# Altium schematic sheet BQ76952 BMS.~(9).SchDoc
size A3; SheetNumber: 9; SheetTotal: 9
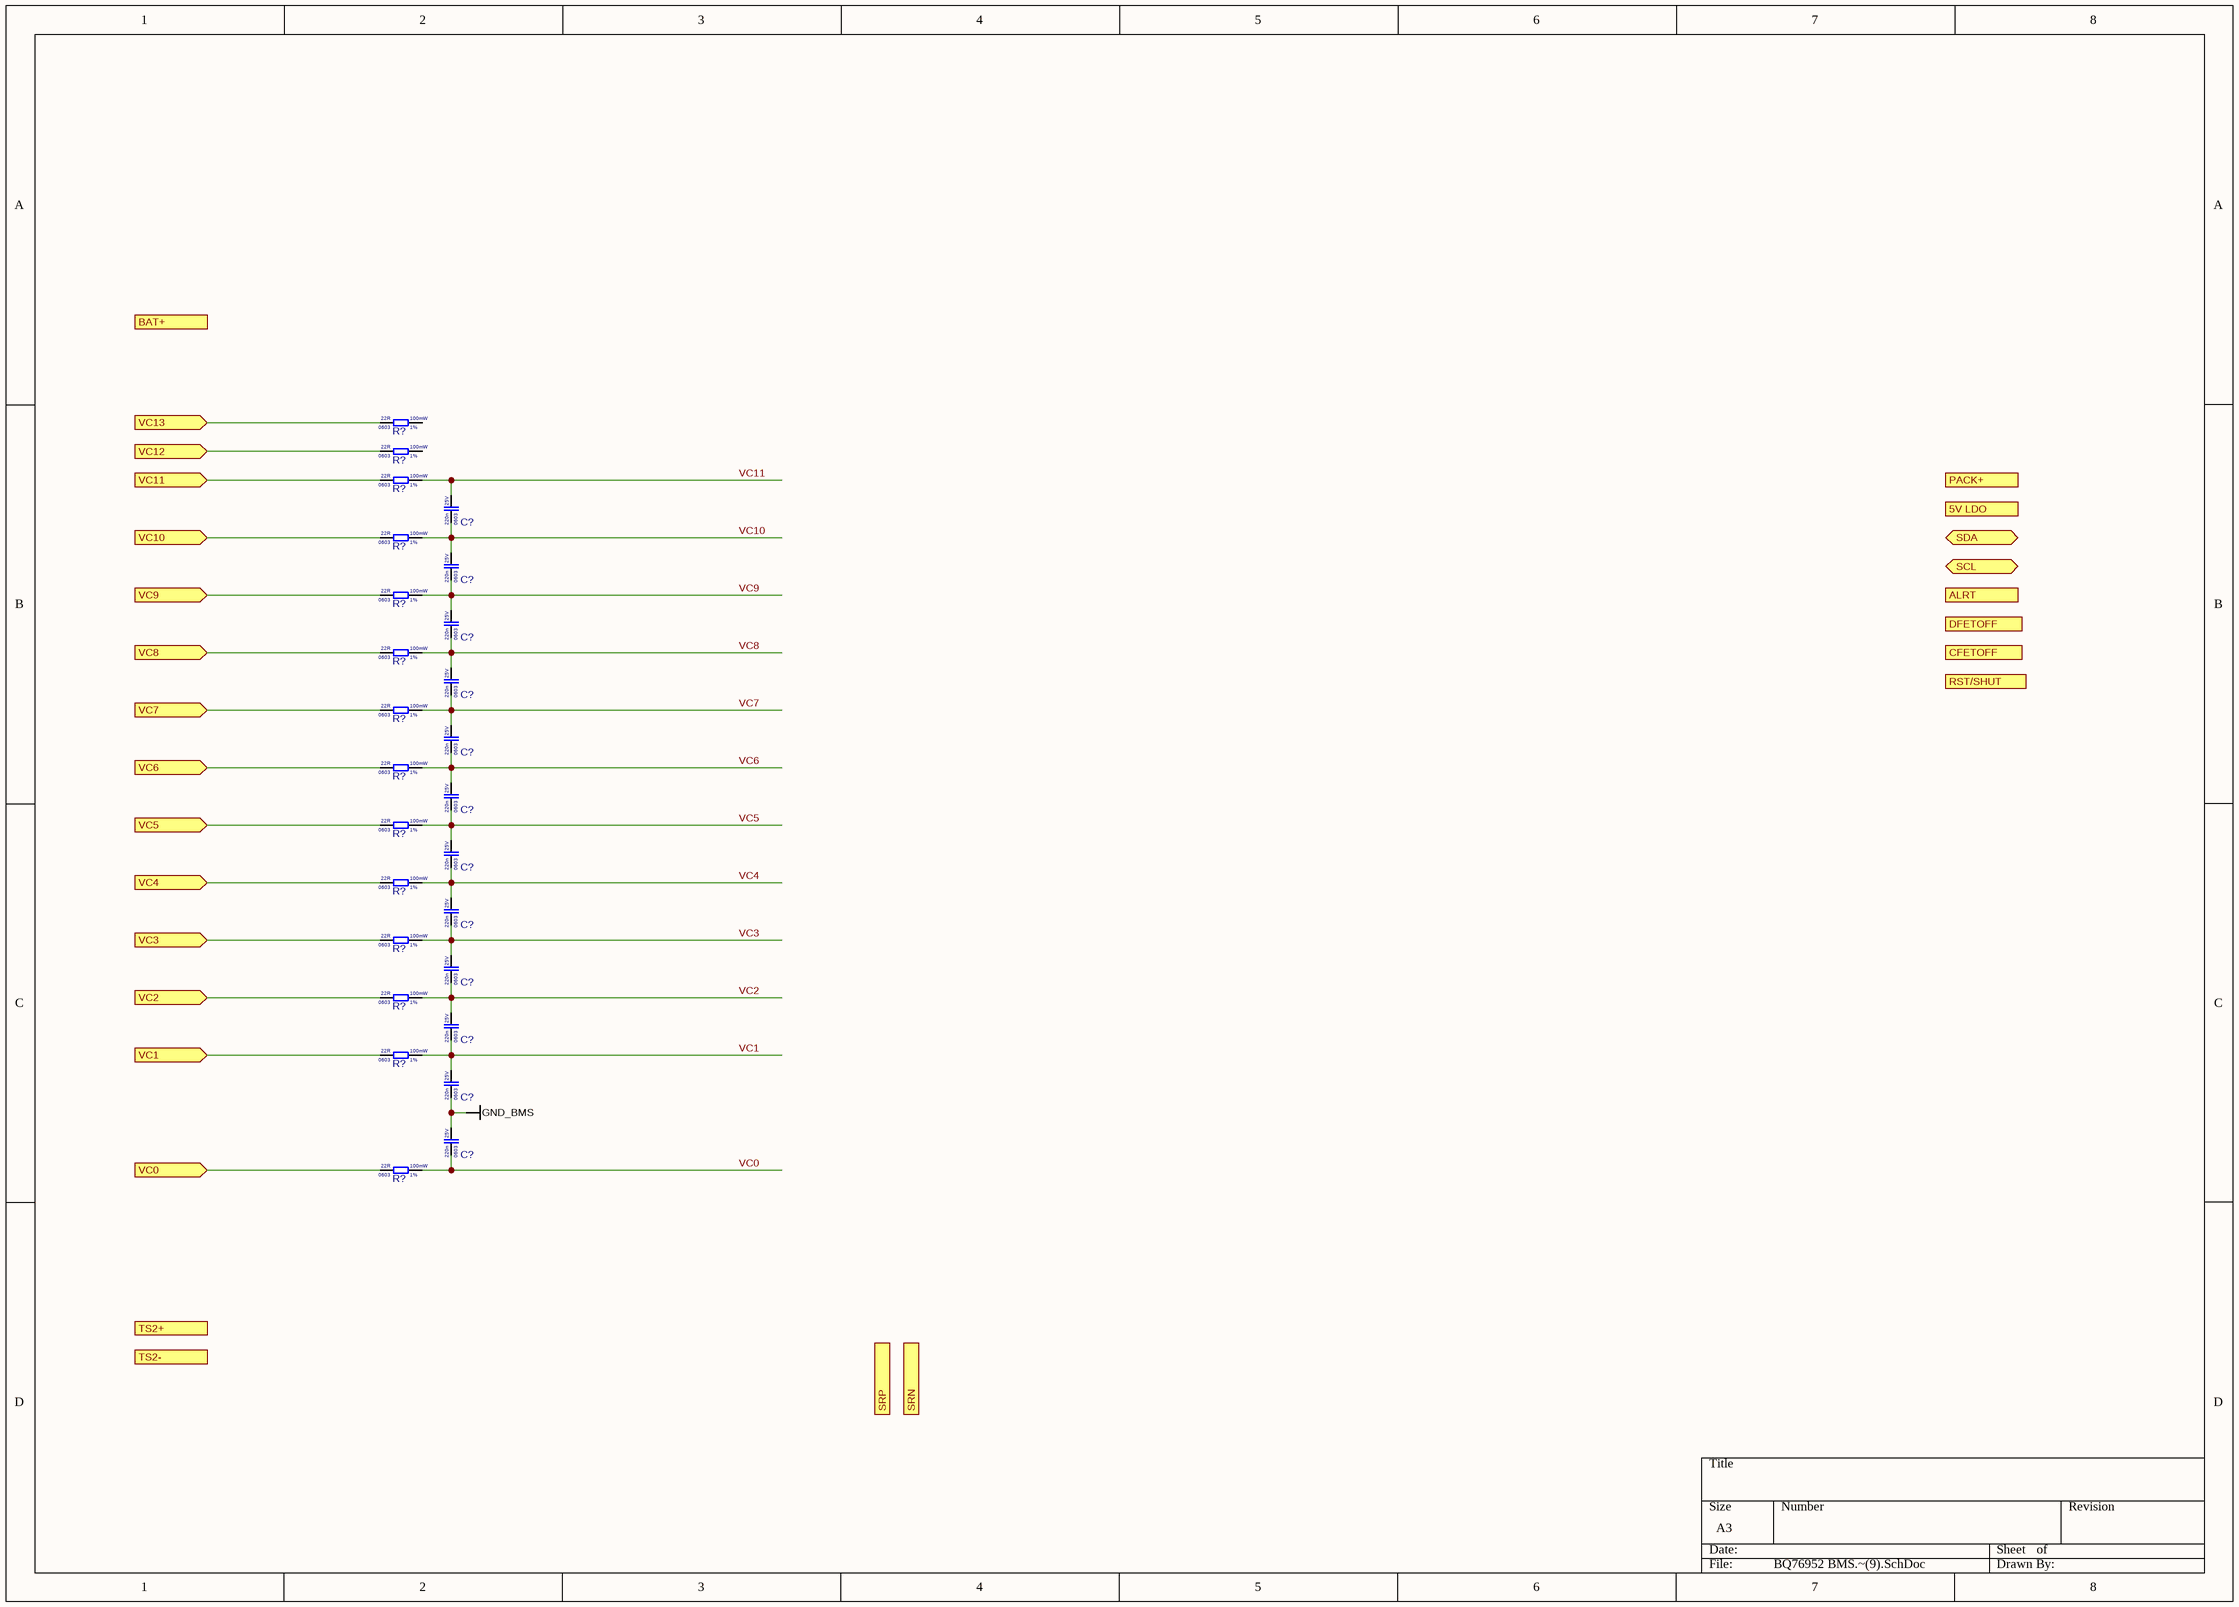
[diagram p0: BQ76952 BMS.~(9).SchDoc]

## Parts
(Parts that share a designator on the sheet are numbered #1, #2 ... from top to bottom, then left to right.)
C?#1  Voltage Rating: 25V  Case Code (Imperial): 0603  Capacitance: 220n  [CAP 0603]  (hidden comment: CL10B224KA8NNNC)
C?#2  Voltage Rating: 25V  Case Code (Imperial): 0603  Capacitance: 220n  [CAP 0603]  (hidden comment: CL10B224KA8NNNC)
C?#3  Voltage Rating: 25V  Case Code (Imperial): 0603  Capacitance: 220n  [CAP 0603]  (hidden comment: CL10B224KA8NNNC)
C?#4  Voltage Rating: 25V  Case Code (Imperial): 0603  Capacitance: 220n  [CAP 0603]  (hidden comment: CL10B224KA8NNNC)
C?#5  Voltage Rating: 25V  Case Code (Imperial): 0603  Capacitance: 220n  [CAP 0603]  (hidden comment: CL10B224KA8NNNC)
C?#6  Voltage Rating: 25V  Case Code (Imperial): 0603  Capacitance: 220n  [CAP 0603]  (hidden comment: CL10B224KA8NNNC)
C?#7  Voltage Rating: 25V  Case Code (Imperial): 0603  Capacitance: 220n  [CAP 0603]  (hidden comment: CL10B224KA8NNNC)
C?#8  Voltage Rating: 25V  Case Code (Imperial): 0603  Capacitance: 220n  [CAP 0603]  (hidden comment: CL10B224KA8NNNC)
C?#9  Voltage Rating: 25V  Case Code (Imperial): 0603  Capacitance: 220n  [CAP 0603]  (hidden comment: CL10B224KA8NNNC)
C?#10  Voltage Rating: 25V  Case Code (Imperial): 0603  Capacitance: 220n  [CAP 0603]  (hidden comment: CL10B224KA8NNNC)
C?#11  Voltage Rating: 25V  Case Code (Imperial): 0603  Capacitance: 220n  [CAP 0603]  (hidden comment: CL10B224KA8NNNC)
C?#12  Voltage Rating: 25V  Case Code (Imperial): 0603  Capacitance: 220n  [CAP 0603]  (hidden comment: CL10B224KA8NNNC)
R?#1  Resistance Tolerance: 1%  Resistance: 22R  Power Rating: 100mW  Case Code (Imperial): 0603  [RES_0603]  (hidden comment: 0603WAF220JT5E)
R?#2  Resistance Tolerance: 1%  Resistance: 22R  Power Rating: 100mW  Case Code (Imperial): 0603  [RES_0603]  (hidden comment: 0603WAF220JT5E)
R?#3  Resistance Tolerance: 1%  Resistance: 22R  Power Rating: 100mW  Case Code (Imperial): 0603  [RES_0603]  (hidden comment: 0603WAF220JT5E)
R?#4  Resistance Tolerance: 1%  Resistance: 22R  Power Rating: 100mW  Case Code (Imperial): 0603  [RES_0603]  (hidden comment: 0603WAF220JT5E)
R?#5  Resistance Tolerance: 1%  Resistance: 22R  Power Rating: 100mW  Case Code (Imperial): 0603  [RES_0603]  (hidden comment: 0603WAF220JT5E)
R?#6  Resistance Tolerance: 1%  Resistance: 22R  Power Rating: 100mW  Case Code (Imperial): 0603  [RES_0603]  (hidden comment: 0603WAF220JT5E)
R?#7  Resistance Tolerance: 1%  Resistance: 22R  Power Rating: 100mW  Case Code (Imperial): 0603  [RES_0603]  (hidden comment: 0603WAF220JT5E)
R?#8  Resistance Tolerance: 1%  Resistance: 22R  Power Rating: 100mW  Case Code (Imperial): 0603  [RES_0603]  (hidden comment: 0603WAF220JT5E)
R?#9  Resistance Tolerance: 1%  Resistance: 22R  Power Rating: 100mW  Case Code (Imperial): 0603  [RES_0603]  (hidden comment: 0603WAF220JT5E)
R?#10  Resistance Tolerance: 1%  Resistance: 22R  Power Rating: 100mW  Case Code (Imperial): 0603  [RES_0603]  (hidden comment: 0603WAF220JT5E)
R?#11  Resistance Tolerance: 1%  Resistance: 22R  Power Rating: 100mW  Case Code (Imperial): 0603  [RES_0603]  (hidden comment: 0603WAF220JT5E)
R?#12  Resistance Tolerance: 1%  Resistance: 22R  Power Rating: 100mW  Case Code (Imperial): 0603  [RES_0603]  (hidden comment: 0603WAF220JT5E)
R?#13  Resistance Tolerance: 1%  Resistance: 22R  Power Rating: 100mW  Case Code (Imperial): 0603  [RES_0603]  (hidden comment: 0603WAF220JT5E)
R?#14  Resistance Tolerance: 1%  Resistance: 22R  Power Rating: 100mW  Case Code (Imperial): 0603  [RES_0603]  (hidden comment: 0603WAF220JT5E)

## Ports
5V LDO (out, see BMS[3A]), ALRT (out, see BMS[3B]), BAT+ (in, see BMS[2A], BMS[1A]), CFETOFF (in, see BMS[3C]), DFETOFF (in, see BMS[3B]), PACK+ (out, see BMS[3A], BMS[8A], Charger BQ25756[1A], CHARGER[1B], Power distribution[3A]), RST/SHUT (in, see BMS[3B]), SCL (bidir, see BMS[3C], BMS[8C]), SDA (bidir, see BMS[3C], BMS[8C]), SRN (in, see BMS[3C]), SRP (in, see BMS[2C]), TS2+ (in, see BMS[2C], BMS[1C]), TS2- (in, see BMS[2C], BMS[1C]), VC0 (in, see BMS[2C], BMS[1C]), VC1 (in, see BMS[2B], BMS[1B]), VC2 (in, see BMS[2B], BMS[1B]), VC3 (in, see BMS[2B], BMS[1B]), VC4 (in, see BMS[2B], BMS[1B]), VC5 (in, see BMS[2B], BMS[1B]), VC6 (in, see BMS[2B], BMS[1B]), VC7 (in, see BMS[2B], BMS[1B]), VC8 (in, see BMS[2B], BMS[1B]), VC9 (in, see BMS[2B], BMS[1B]), VC10 (in, see BMS[2B], BMS[1B]), VC11 (in, see BMS[2B], BMS[1B]), VC12 (in, see BMS[2B], BMS[1B]), VC13 (in, see BMS[2B], BMS[1B])

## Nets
GND_BMS: C?#11.1 C?#12.2
VC0: R?#14.1 ; port VC0
VC0: C?#12.1 R?#14.2  [a separate net that carries the same name]
VC1: R?#13.1 ; port VC1
VC1: C?#10.1 C?#11.2 R?#13.2  [a separate net that carries the same name]
VC2: R?#12.1 ; port VC2
VC2: C?#9.1 C?#10.2 R?#12.2  [a separate net that carries the same name]
VC3: R?#11.1 ; port VC3
VC3: C?#8.1 C?#9.2 R?#11.2  [a separate net that carries the same name]
VC4: R?#10.1 ; port VC4
VC4: C?#7.1 C?#8.2 R?#10.2  [a separate net that carries the same name]
VC5: R?#9.1 ; port VC5
VC5: C?#6.1 C?#7.2 R?#9.2  [a separate net that carries the same name]
VC6: R?#8.1 ; port VC6
VC6: C?#5.1 C?#6.2 R?#8.2  [a separate net that carries the same name]
VC7: R?#7.1 ; port VC7
VC7: C?#4.1 C?#5.2 R?#7.2  [a separate net that carries the same name]
VC8: R?#6.1 ; port VC8
VC8: C?#3.1 C?#4.2 R?#6.2  [a separate net that carries the same name]
VC9: R?#5.1 ; port VC9
VC9: C?#2.1 C?#3.2 R?#5.2  [a separate net that carries the same name]
VC10: R?#4.1 ; port VC10
VC10: C?#1.1 C?#2.2 R?#4.2  [a separate net that carries the same name]
VC11: R?#3.1 ; port VC11
VC11: C?#1.2 R?#3.2  [a separate net that carries the same name]
VC12: R?#2.1 ; port VC12
VC13: R?#1.1 ; port VC13

Not connected (* = marked no-connect by the designer): R?#1 2; R?#2 2

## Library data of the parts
C?#1-C?#12 = CL10B224KA8NNNC: Cap 220nF 25V 0603 X7R; Manufacturer: Samsung
R?#1-R?#14 = 0603WAF220JT5E: Res 22R 0603 1% 100mW 75V; Manufacturer: Uni-Royal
